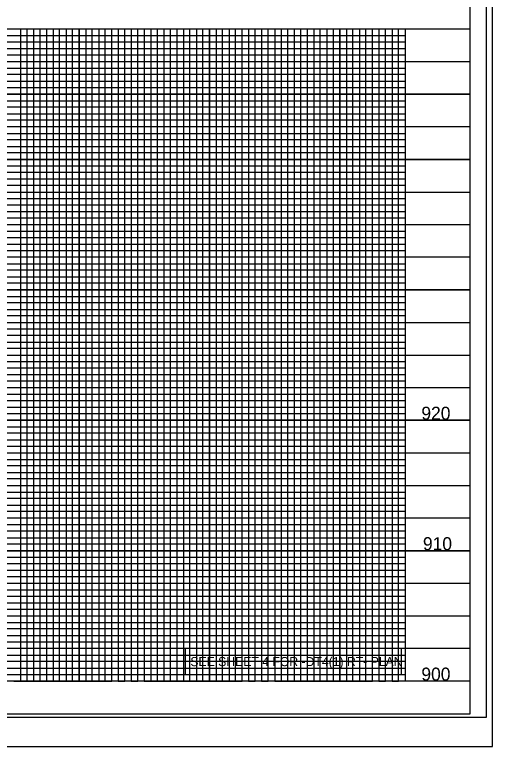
# Model space of a CAD drawing. Extents: x 1648123 to 1650776, y 802691 to 803791.
# Drawn here: x 1650180 to 1650546, y 802691 to 803252 of the extents above; entities that cross this region are included whole.
import ezdxf

# ---------------------------------------------------------------- set-up
doc = ezdxf.new("R2010")
doc.units = 0
for name, color, linetype in [('Exist Vertical Profile Vertical Axis Label', 7, 'Continuous'), ('Prop Dimension', 7, 'Continuous'), ('Prop Grid Mask', 7, 'Continuous'), ('Sheet Cutting Line CELL', 7, 'Continuous'), ('Sheet DOT Grid CELL', 7, 'Continuous'), ('Sheet Layout Profile Border Port 2', 7, 'Continuous'), ('Sheet Plot Border Inside CELL', 7, 'Continuous'), ('Sheet Plot Border Outside CELL', 7, 'Continuous'), ('Sheet Profile CELL', 7, 'Continuous'), ('Sheet Profile Grid Major CELL', 7, 'Continuous'), ('Sheet Profile Grid Middle CELL', 7, 'Continuous'), ('Sheet Profile Grid Minor CELL', 7, 'Continuous')]:
    doc.layers.add(name, color=color, linetype=linetype)

msp = doc.modelspace()

# ---------------------------------------------------------------- linework, layer by layer
at = {"layer": 'Prop Grid Mask'}
msp.add_lwpolyline([(1650310.67, 802766.02), (1650310.67, 802746.02), (1650476.65, 802746.02), (1650476.65, 802766.02)], close=True, dxfattribs=at)
at = {"layer": 'Sheet Cutting Line CELL'}
msp.add_line((1648862.28, 802691.02), (1650546.28, 802691.02), dxfattribs=at)
at = {"layer": 'Sheet DOT Grid CELL'}
for p, q in [((1649029.28, 803241.02), (1650529.17, 803241.02)), ((1650229.28, 803241.02), (1650229.28, 802741.02)), ((1650279.28, 803241.02), (1650279.28, 802741.02)), ((1650329.28, 803241.02), (1650329.28, 802741.02)), ((1650379.28, 803241.02), (1650379.28, 802741.02)), ((1650429.28, 803241.02), (1650429.28, 802741.02)), ((1650479.28, 803241.02), (1650479.28, 802741.02)), ((1649029.28, 803191.02), (1650529.17, 803191.02)), ((1649029.28, 803141.02), (1650529.17, 803141.02)), ((1649029.28, 803091.02), (1650529.17, 803091.02)), ((1649029.28, 803041.02), (1650529.17, 803041.02)), ((1649029.28, 802991.02), (1650529.17, 802991.02)), ((1649029.28, 802941.02), (1650529.17, 802941.02)), ((1649029.28, 802891.02), (1650529.17, 802891.02)), ((1649029.28, 802841.02), (1650529.17, 802841.02)), ((1649029.28, 802791.02), (1650529.17, 802791.02))]:
    msp.add_line(p, q, dxfattribs=at)
at = {"layer": 'Sheet Layout Profile Border Port 2'}
msp.add_lwpolyline([(1649079.28, 803241.02), (1650479.28, 803241.02), (1650479.28, 802741.02), (1649079.28, 802741.02)], close=True, dxfattribs=at)
at = {"layer": 'Sheet Plot Border Inside CELL'}
msp.add_lwpolyline([(1648875.28, 802713.47), (1650541.78, 802713.47), (1650541.78, 803768.57), (1648875.28, 803768.57)], close=True, dxfattribs=at)
at = {"layer": 'Sheet Plot Border Outside CELL'}
msp.add_lwpolyline([(1648862.28, 802691.02), (1650546.28, 802691.02), (1650546.28, 803791.02), (1648862.28, 803791.02)], close=True, dxfattribs=at)
at = {"layer": 'Sheet Profile CELL'}
for p, q in [((1649029.28, 803241.02), (1650529.28, 803241.02)), ((1650529.28, 802741.02), (1649029.28, 802741.02)), ((1649029.28, 802716.02), (1650529.28, 802716.02))]:
    msp.add_line(p, q, dxfattribs=at)
msp.add_lwpolyline([(1650529.28, 803766.02), (1649029.28, 803766.02), (1649029.28, 802716.02), (1650529.28, 802716.02)], close=True, dxfattribs=at)
at = {"layer": 'Sheet Profile Grid Major CELL'}
for p, q in [((1650229.28, 803241.02), (1650279.28, 803241.02)), ((1650329.28, 803241.02), (1650379.28, 803241.02)), ((1650429.28, 803241.02), (1650479.28, 803241.02)), ((1650429.28, 802741.02), (1650429.28, 802741.02))]:
    msp.add_line(p, q, dxfattribs=at)
for points in [[(1650179.28, 802741.02), (1650229.28, 802741.02), (1650229.28, 803241.02), (1650279.28, 803241.02), (1650279.28, 802741.02), (1650329.28, 802741.02), (1650329.28, 803241.02), (1650379.28, 803241.02), (1650379.28, 802741.02), (1650429.28, 802741.02), (1650429.28, 802741.02), (1650429.28, 803241.02), (1650479.28, 803241.02), (1650479.28, 802741.02)], [(1650529.28, 803191.02), (1649029.28, 803191.02)], [(1650529.28, 803141.02), (1649029.28, 803141.02), (1649029.28, 803091.02), (1650529.28, 803091.02)], [(1650529.28, 803041.02), (1649029.28, 803041.02), (1649029.28, 802991.02), (1650529.28, 802991.02)], [(1650529.28, 802941.02), (1649029.28, 802941.02), (1649029.28, 802891.02), (1650529.28, 802891.02)], [(1650529.28, 802841.02), (1649029.28, 802841.02), (1649029.28, 802841.02), (1649029.28, 802791.02), (1650529.28, 802791.02)], [(1650529.28, 802741.02), (1649029.28, 802741.02)]]:
    msp.add_lwpolyline(points, dxfattribs=at)
at = {"layer": 'Sheet Profile Grid Middle CELL'}
for points in [[(1650154.28, 803241.02), (1650204.28, 803241.02), (1650204.28, 802741.02), (1650254.28, 802741.02), (1650254.28, 803241.02), (1650304.28, 803241.02), (1650304.28, 802741.02), (1650354.28, 802741.02), (1650354.28, 803241.02), (1650404.28, 803241.02), (1650404.28, 802741.02), (1650454.28, 802741.02), (1650454.28, 803241.02)], [(1649029.28, 803216.02), (1650529.28, 803216.02)], [(1650529.28, 803166.02), (1649029.28, 803166.02), (1649029.28, 803116.02), (1650529.28, 803116.02)], [(1650529.28, 803066.02), (1649029.28, 803066.02), (1649029.28, 803016.02), (1650529.28, 803016.02)], [(1650529.28, 802966.02), (1649029.28, 802966.02), (1649029.28, 802916.02), (1650529.28, 802916.02)], [(1650529.28, 802866.02), (1649029.28, 802866.02), (1649029.28, 802816.02), (1650529.28, 802816.02)], [(1650529.28, 802766.02), (1649029.28, 802766.02)]]:
    msp.add_lwpolyline(points, dxfattribs=at)
at = {"layer": 'Sheet Profile Grid Minor CELL'}
for p, q in [((1649079.28, 803236.02), (1650479.28, 803236.02)), ((1650479.28, 803231.02), (1649079.28, 803231.02)), ((1649079.28, 803226.02), (1650479.28, 803226.02)), ((1650479.28, 803221.02), (1649079.28, 803221.02)), ((1649079.28, 803211.02), (1650479.28, 803211.02)), ((1650479.28, 803206.02), (1649079.28, 803206.02)), ((1649079.28, 803201.02), (1650479.28, 803201.02)), ((1650479.28, 803196.02), (1649079.28, 803196.02)), ((1649079.28, 803186.02), (1650479.28, 803186.02)), ((1650479.28, 803181.02), (1649079.28, 803181.02)), ((1649079.28, 803176.02), (1650479.28, 803176.02)), ((1650479.28, 803171.02), (1649079.28, 803171.02)), ((1649079.28, 803161.02), (1650479.28, 803161.02)), ((1650479.28, 803156.02), (1649079.28, 803156.02)), ((1649079.28, 803151.02), (1650479.28, 803151.02)), ((1650479.28, 803146.02), (1649079.28, 803146.02)), ((1649079.28, 803136.02), (1650479.28, 803136.02)), ((1650479.28, 803131.02), (1649079.28, 803131.02)), ((1649079.28, 803126.02), (1650479.28, 803126.02)), ((1650479.28, 803121.02), (1649079.28, 803121.02)), ((1649079.28, 803111.02), (1650479.28, 803111.02)), ((1650479.28, 803106.02), (1649079.28, 803106.02)), ((1649079.28, 803101.02), (1650479.28, 803101.02)), ((1650479.28, 803096.02), (1649079.28, 803096.02)), ((1649079.28, 803086.02), (1650479.28, 803086.02)), ((1650479.28, 803081.02), (1649079.28, 803081.02)), ((1649079.28, 803076.02), (1650479.28, 803076.02)), ((1650479.28, 803071.02), (1649079.28, 803071.02)), ((1649079.28, 803061.02), (1650479.28, 803061.02)), ((1650479.28, 803056.02), (1649079.28, 803056.02)), ((1649079.28, 803051.02), (1650479.28, 803051.02)), ((1650479.28, 803046.02), (1649079.28, 803046.17)), ((1649079.28, 803036.02), (1650479.28, 803036.02)), ((1650479.28, 803031.02), (1649079.28, 803031.02)), ((1649079.28, 803026.02), (1650479.28, 803026.02)), ((1650479.28, 803021.02), (1649079.28, 803021.02)), ((1649079.28, 803011.02), (1650479.28, 803011.02)), ((1650479.28, 803006.02), (1649079.28, 803006.02)), ((1649079.28, 803001.02), (1650479.28, 803001.02)), ((1650479.28, 802996.02), (1649079.28, 802996.02)), ((1649079.28, 802986.02), (1650479.28, 802986.02)), ((1650479.28, 802981.02), (1649079.28, 802981.02)), ((1649079.28, 802976.02), (1650479.28, 802976.02)), ((1650479.28, 802971.02), (1649079.28, 802971.02)), ((1649079.28, 802961.02), (1650479.28, 802961.02)), ((1650479.28, 802956.02), (1649079.28, 802956.02)), ((1649079.28, 802951.02), (1650479.28, 802951.02)), ((1650479.28, 802946.02), (1649079.28, 802946.02)), ((1649079.28, 802936.02), (1650479.28, 802936.02)), ((1650479.28, 802931.02), (1649079.28, 802931.02)), ((1649079.28, 802926.02), (1650479.28, 802926.02)), ((1650479.28, 802921.02), (1649079.28, 802921.02)), ((1649079.28, 802911.02), (1650479.28, 802911.02)), ((1650479.28, 802906.02), (1649079.28, 802906.02)), ((1649079.28, 802901.02), (1650479.28, 802901.02)), ((1650479.28, 802896.02), (1649079.28, 802896.02)), ((1649079.28, 802886.02), (1650479.28, 802886.02)), ((1650479.28, 802881.02), (1649079.28, 802881.02)), ((1649079.28, 802876.02), (1650479.28, 802876.02)), ((1650479.28, 802871.02), (1649079.28, 802871.02)), ((1649079.28, 802861.02), (1650479.28, 802861.02)), ((1650479.28, 802856.02), (1649079.28, 802856.02)), ((1649079.28, 802851.02), (1650479.28, 802851.02)), ((1650479.28, 802846.02), (1649079.28, 802846.02)), ((1649079.28, 802836.02), (1650479.28, 802836.02)), ((1650479.28, 802831.02), (1649079.28, 802831.02)), ((1649079.28, 802826.02), (1650479.28, 802826.02)), ((1650479.28, 802821.02), (1649079.28, 802821.02)), ((1649079.28, 802811.02), (1650479.28, 802811.02)), ((1650479.28, 802806.02), (1649079.28, 802806.02)), ((1649079.28, 802801.02), (1650479.28, 802801.02)), ((1650479.28, 802796.02), (1649079.28, 802796.02)), ((1649079.28, 802786.02), (1650479.28, 802786.02)), ((1650479.28, 802781.02), (1649079.28, 802781.02)), ((1649079.28, 802776.02), (1650479.28, 802776.02)), ((1650479.28, 802771.02), (1649079.28, 802771.02)), ((1649079.28, 802761.02), (1650479.28, 802761.02)), ((1650479.28, 802756.02), (1649079.28, 802756.02)), ((1649079.28, 802751.02), (1650479.28, 802751.02)), ((1649079.28, 802746.02), (1650479.28, 802746.02)), ((1650479.28, 802746.02), (1650479.28, 802746.02))]:
    msp.add_line(p, q, dxfattribs=at)
for points in [[(1650174.28, 803241.02), (1650184.28, 803241.02), (1650184.28, 802741.02), (1650189.28, 802741.02), (1650189.28, 803241.02), (1650194.28, 803241.02), (1650194.28, 802741.02), (1650199.28, 802741.02), (1650199.28, 803241.02), (1650209.28, 803241.02), (1650209.28, 802741.02), (1650214.28, 802741.02), (1650214.28, 803241.02), (1650219.28, 803241.02), (1650219.28, 802741.02)], [(1650219.28, 802741.02), (1650224.28, 802741.02), (1650224.28, 803241.02), (1650234.28, 803241.02), (1650234.28, 802741.02), (1650239.28, 802741.02), (1650239.28, 803241.02), (1650244.28, 803241.02), (1650244.28, 802741.02), (1650249.28, 802741.02), (1650249.28, 803241.02), (1650259.28, 803241.02), (1650259.28, 802741.02), (1650264.28, 802741.02), (1650264.28, 803241.02), (1650269.28, 803241.02), (1650269.28, 802741.02), (1650274.28, 802741.02), (1650274.28, 803241.02), (1650284.28, 803241.02), (1650284.28, 802741.02), (1650289.28, 802741.02), (1650289.28, 803241.02), (1650294.28, 803241.02), (1650294.28, 802741.02), (1650299.28, 802741.02), (1650299.28, 803241.02), (1650309.28, 803241.02), (1650309.28, 802741.02), (1650314.28, 802741.02), (1650314.28, 803241.02), (1650319.28, 803241.02), (1650319.28, 802741.02), (1650324.28, 802741.02), (1650324.28, 803241.02), (1650334.28, 803241.02), (1650334.28, 802741.02), (1650339.28, 802741.02), (1650339.28, 803241.02), (1650344.28, 803241.02), (1650344.28, 802741.02), (1650349.28, 802741.02), (1650349.28, 803241.02), (1650359.28, 803241.02), (1650359.28, 802741.02), (1650364.28, 802741.02), (1650364.28, 803241.02), (1650369.28, 803241.02), (1650369.28, 802741.02), (1650374.28, 802741.02), (1650374.28, 803241.02), (1650384.28, 803241.02), (1650384.28, 802741.02), (1650389.28, 802741.02), (1650389.28, 803241.02), (1650394.28, 803241.02), (1650394.28, 802741.02), (1650399.28, 802741.02), (1650399.28, 803241.02), (1650409.28, 803241.02), (1650409.28, 802741.02), (1650414.28, 802741.02), (1650414.28, 803241.02), (1650419.28, 803241.02), (1650419.28, 802741.02), (1650424.28, 802741.02), (1650424.28, 803241.02), (1650434.28, 803241.02), (1650434.28, 802741.02), (1650439.28, 802741.02), (1650439.28, 803241.02), (1650444.28, 803241.02), (1650444.28, 802741.02), (1650449.28, 802741.02), (1650449.28, 803241.02), (1650459.28, 803241.02), (1650459.28, 802741.02), (1650464.28, 802741.02), (1650464.28, 803241.02), (1650469.28, 803241.02), (1650469.28, 802741.02), (1650474.28, 802741.02), (1650474.28, 803241.02), (1650479.28, 803241.02)]]:
    msp.add_lwpolyline(points, dxfattribs=at)

# ---------------------------------------------------------------- texts
at = {"layer": 'Exist Vertical Profile Vertical Axis Label'}
for s, p in [('920', (1650491.81, 802941.41)), ('910', (1650493.01, 802841.41)), ('900', (1650491.81, 802741.41))]:
    msp.add_text(s, height=10, dxfattribs=at).set_placement(p)
at = {"layer": 'Prop Dimension'}
msp.add_text('SEE SHEET 4 FOR -DT4(1) RT- PLAN', height=7, dxfattribs=at).set_placement((1650314.59, 802752.52))

doc.saveas('drawing.dxf')
